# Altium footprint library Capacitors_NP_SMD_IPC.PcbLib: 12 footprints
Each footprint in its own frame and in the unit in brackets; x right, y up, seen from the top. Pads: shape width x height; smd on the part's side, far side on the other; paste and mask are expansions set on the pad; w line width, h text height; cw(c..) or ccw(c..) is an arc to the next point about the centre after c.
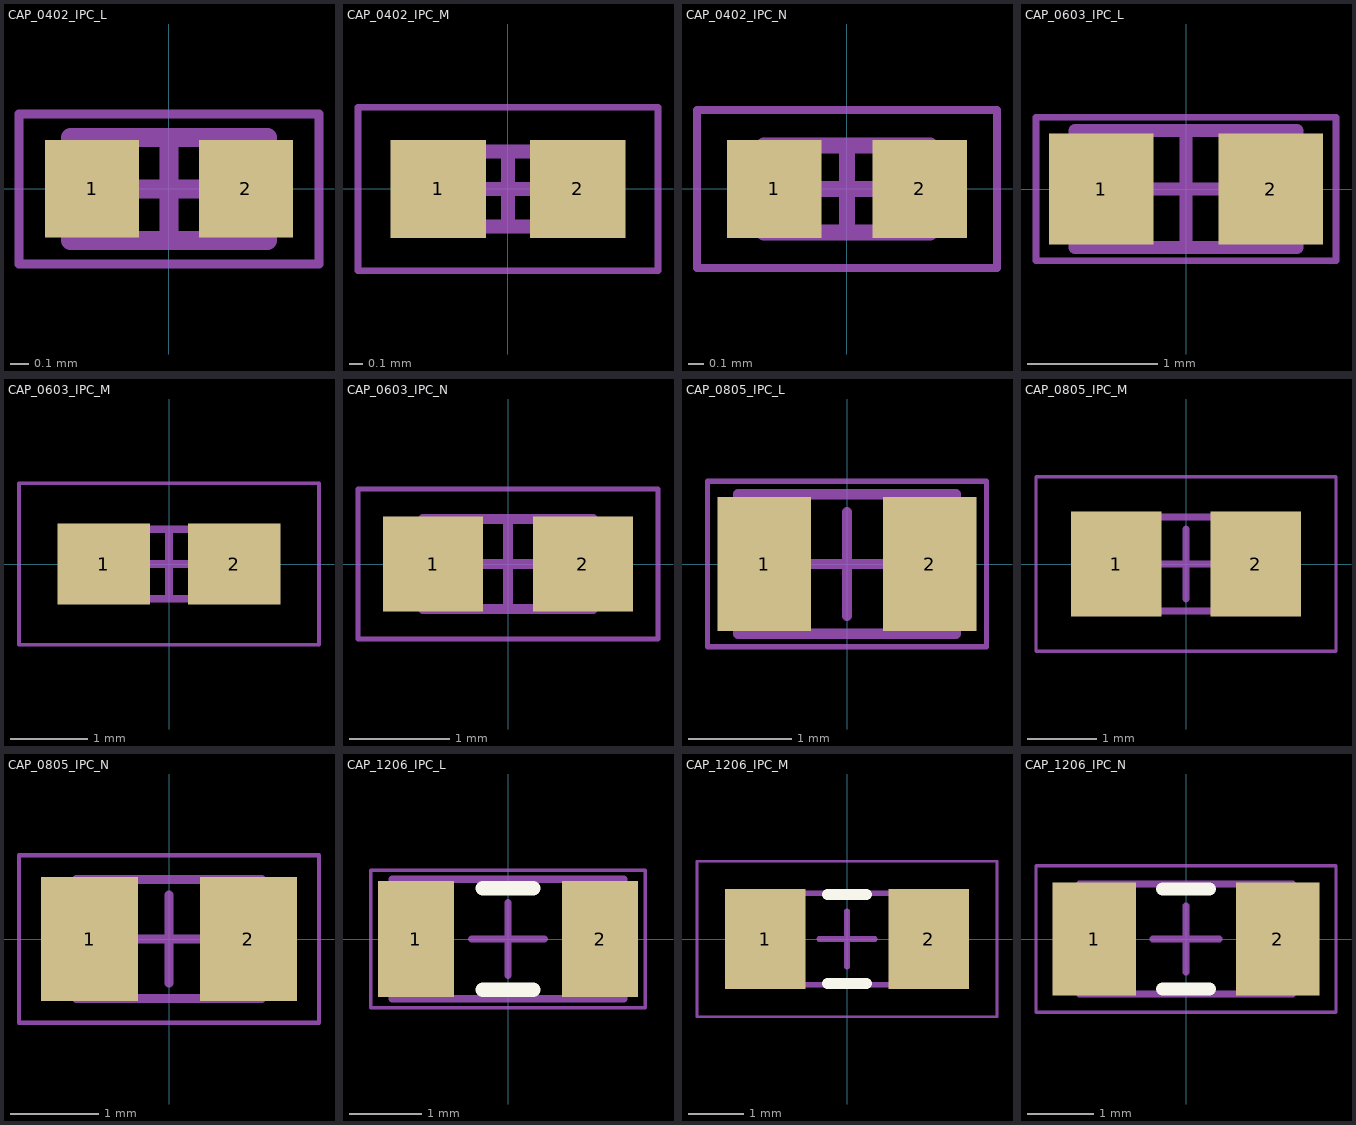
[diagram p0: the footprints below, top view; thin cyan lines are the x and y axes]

## CAP_0402_IPC_L [mm] "Chip capacitor 0402 (1.00x0.50x0.35mm) - IPC Least"
height 0.4
pads (2):
  rect 0.5x0.52 smd: 1(-0.41,0) 2(0.41,0)
Mechanical 13:
  lines w0.1: -0.525,-0.275 0.525,-0.275 0.525,0.275 -0.525,0.275 -0.525,-0.275
Mechanical 15:
  lines w0.05: -0.8,-0.4 0.8,-0.4 0.8,0.4 -0.8,0.4 -0.8,-0.4
  lines w0.1: -0.275,0 0.275,0 ; 0,-0.275 0,0.275
3D body "CAPC1005X04L.step": height 0.4, standoff 0, extent -0.525,-0.275 0.525,0.275

## CAP_0402_IPC_M [mm] "Chip capacitor 0402 (1.00x0.50x0.35mm) - IPC Most"
height 0.4
pads (2):
  rect 0.7x0.72 smd: 1(-0.51,0) 2(0.51,0)
Mechanical 13:
  lines w0.1: -0.525,-0.275 0.525,-0.275 0.525,0.275 -0.525,0.275 -0.525,-0.275
Mechanical 15:
  lines w0.05: -1.1,-0.6 1.1,-0.6 1.1,0.6 -1.1,0.6 -1.1,-0.6
  lines w0.1: -0.275,0 0.275,0 ; 0,-0.275 0,0.275
3D body "CAPC1005X04M.step": height 0.4, standoff 0, extent -0.525,-0.275 0.525,0.275

## CAP_0402_IPC_N [mm] "Chip capacitor 0402 (1.00x0.50x0.35mm) - IPC Nominal"
height 0.4
pads (2):
  rect 0.6x0.62 smd: 1(-0.46,0) 2(0.46,0)
Mechanical 13:
  lines w0.1: -0.525,-0.275 0.525,-0.275 0.525,0.275 -0.525,0.275 -0.525,-0.275
Mechanical 15:
  lines w0.05: -0.95,-0.5 0.95,-0.5 0.95,0.5 -0.95,0.5 -0.95,-0.5
  lines w0.1: -0.275,0 0.275,0 ; 0,-0.275 0,0.275
3D body "CAPC1005X04N.step": height 0.4, standoff 0, extent -0.525,-0.275 0.525,0.275

## CAP_0603_IPC_L [mm] "Chip capacitor 0603 (1.60x0.80x0.45mm) - IPC Least"
height 0.55
pads (2):
  rect 0.8x0.85 smd: 1(-0.65,0) 2(0.65,0)
Mechanical 13:
  lines w0.1: -0.85,-0.45 0.85,-0.45 0.85,0.45 -0.85,0.45 -0.85,-0.45
Mechanical 15:
  lines w0.05: -1.15,-0.55 1.15,-0.55 1.15,0.55 -1.15,0.55 -1.15,-0.55
  lines w0.1: -0.45,0 0.45,0 ; 0,-0.45 0,0.45
3D body "CAPC1608X06L.step": height 0.55, standoff 0, extent -0.85,-0.45 0.85,0.45

## CAP_0603_IPC_M [mm] "Chip capacitor 0603 (1.60x0.80x0.45mm) - IPC Most"
height 0.55
pads (2):
  rect 1.2x1.05 smd: 1(-0.85,0) 2(0.85,0)
Mechanical 13:
  lines w0.1: -0.85,-0.45 0.85,-0.45 0.85,0.45 -0.85,0.45 -0.85,-0.45
Mechanical 15:
  lines w0.05: -1.95,-1.05 1.95,-1.05 1.95,1.05 -1.95,1.05 -1.95,-1.05
  lines w0.1: -0.45,0 0.45,0 ; 0,-0.45 0,0.45
3D body "CAPC1608X06M.step": height 0.55, standoff 0, extent -0.85,-0.45 0.85,0.45

## CAP_0603_IPC_N [mm] "Chip capacitor 0603 (1.60x0.80x0.45mm) - IPC Nominal"
height 0.55
pads (2):
  rect 1x0.95 smd: 1(-0.75,0) 2(0.75,0)
Mechanical 13:
  lines w0.1: -0.85,-0.45 0.85,-0.45 0.85,0.45 -0.85,0.45 -0.85,-0.45
Mechanical 15:
  lines w0.05: -1.5,-0.75 1.5,-0.75 1.5,0.75 -1.5,0.75 -1.5,-0.75
  lines w0.1: -0.45,0 0.45,0 ; 0,-0.45 0,0.45
3D body "CAPC1608X06N.step": height 0.55, standoff 0, extent -0.85,-0.45 0.85,0.45

## CAP_0805_IPC_L [mm] "Chip capacitor 0805 (2.00x1.25x0.50mm) - IPC Least"
height 0.6
pads (2):
  rect 0.9x1.3 smd: 1(-0.8,0) 2(0.8,0)
Mechanical 13:
  lines w0.1: -1.05,-0.675 1.05,-0.675 1.05,0.675 -1.05,0.675 -1.05,-0.675
Mechanical 15:
  lines w0.05: -1.35,-0.8 1.35,-0.8 1.35,0.8 -1.35,0.8 -1.35,-0.8
  lines w0.1: -0.5,0 0.5,0 ; 0,-0.5 0,0.5
3D body "CAPC2012X06L.step": height 0.6, standoff 0, extent -1.05,-0.675 1.05,0.675

## CAP_0805_IPC_M [mm] "Chip capacitor 0805 (2.00x1.25x0.50mm) - IPC Most"
height 0.6
pads (2):
  rect 1.3x1.5 smd: 1(-1,0) 2(1,0)
Mechanical 13:
  lines w0.1: -1.05,-0.675 1.05,-0.675 1.05,0.675 -1.05,0.675 -1.05,-0.675
Mechanical 15:
  lines w0.05: -2.15,-1.25 2.15,-1.25 2.15,1.25 -2.15,1.25 -2.15,-1.25
  lines w0.1: -0.5,0 0.5,0 ; 0,-0.5 0,0.5
3D body "CAPC2012X06M.step": height 0.6, standoff 0, extent -1.05,-0.675 1.05,0.675

## CAP_0805_IPC_N [mm] "Chip capacitor 0805 (2.00x1.25x0.50mm) - IPC Nominal"
height 0.6
pads (2):
  rect 1.1x1.4 smd: 1(-0.9,0) 2(0.9,0)
Mechanical 13:
  lines w0.1: -1.05,-0.675 1.05,-0.675 1.05,0.675 -1.05,0.675 -1.05,-0.675
Mechanical 15:
  lines w0.05: -1.7,-0.95 1.7,-0.95 1.7,0.95 -1.7,0.95 -1.7,-0.95
  lines w0.1: -0.5,0 0.5,0 ; 0,-0.5 0,0.5
3D body "CAPC2012X06N.step": height 0.6, standoff 0, extent -1.05,-0.675 1.05,0.675

## CAP_1206_IPC_L [mm] "Chip capacitor 1206 (3.10x1.55x0.55mm) - IPC Least"
height 0.65
pads (2):
  rect 1.05x1.6 smd: 1(-1.275,0) 2(1.275,0)
Top Overlay:
  lines w0.2: -0.35,-0.7 0.35,-0.7 ; -0.35,0.7 0.35,0.7
Mechanical 13:
  lines w0.1: -1.6,-0.825 1.6,-0.825 1.6,0.825 -1.6,0.825 -1.6,-0.825
Mechanical 15:
  lines w0.05: -1.9,-0.95 1.9,-0.95 1.9,0.95 -1.9,0.95 -1.9,-0.95
  lines w0.1: -0.5,0 0.5,0 ; 0,-0.5 0,0.5
3D body "CAPC3115X06L.step": height 0.65, standoff 0, extent -1.6,-0.825 1.6,0.825

## CAP_1206_IPC_M [mm] "Chip capacitor 1206 (3.10x1.55x0.55mm) - IPC Most"
height 0.65
pads (2):
  rect 1.45x1.8 smd: 1(-1.475,0) 2(1.475,0)
Top Overlay:
  lines w0.2: -0.35,-0.8 0.35,-0.8 ; -0.35,0.8 0.35,0.8
Mechanical 13:
  lines w0.1: -1.6,-0.825 1.6,-0.825 1.6,0.825 -1.6,0.825 -1.6,-0.825
Mechanical 15:
  lines w0.05: -2.7,-1.4 2.7,-1.4 2.7,1.4 -2.7,1.4 -2.7,-1.4
  lines w0.1: -0.5,0 0.5,0 ; 0,-0.5 0,0.5
3D body "CAPC3115X06M.step": height 0.65, standoff 0, extent -1.6,-0.825 1.6,0.825

## CAP_1206_IPC_N [mm] "Chip capacitor 1206 (3.10x1.55x0.55mm) - IPC Nominal"
height 0.65
pads (2):
  rect 1.25x1.7 smd: 1(-1.375,0) 2(1.375,0)
Top Overlay:
  lines w0.2: -0.35,-0.75 0.35,-0.75 ; -0.35,0.75 0.35,0.75
Mechanical 13:
  lines w0.1: -1.6,-0.825 1.6,-0.825 1.6,0.825 -1.6,0.825 -1.6,-0.825
Mechanical 15:
  lines w0.05: -2.25,-1.1 2.25,-1.1 2.25,1.1 -2.25,1.1 -2.25,-1.1
  lines w0.1: -0.5,0 0.5,0 ; 0,-0.5 0,0.5
3D body "CAPC3115X06N.step": height 0.65, standoff 0, extent -1.6,-0.825 1.6,0.825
